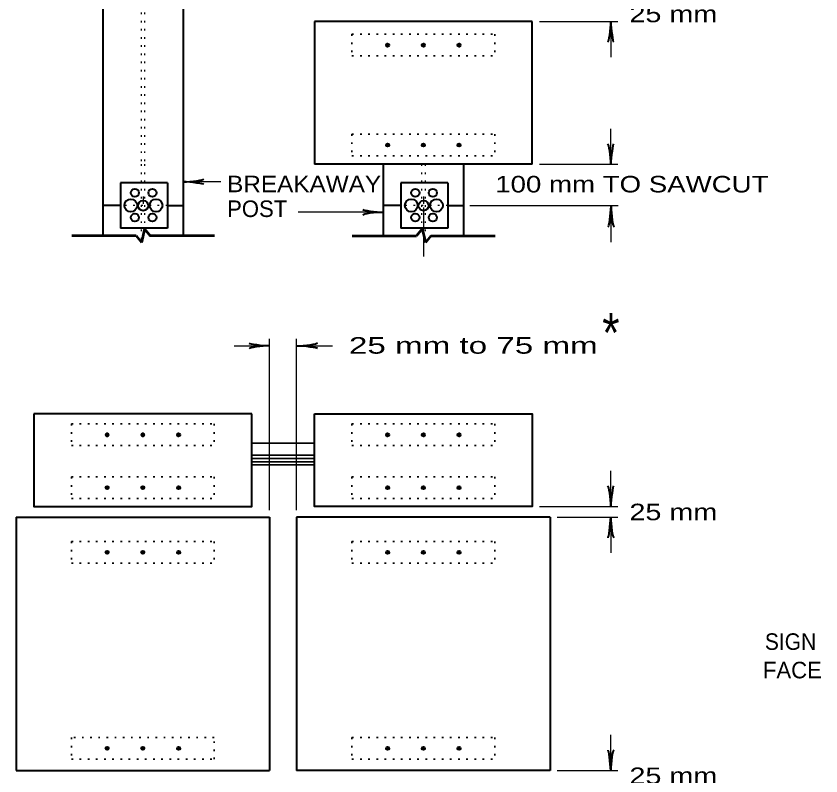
# Model space of a CAD drawing. Extents: x 851 to 1706, y -23 to 521.
# Drawn here: x 1210.4 to 1358.3, y 164.2 to 303.9 of the extents above; entities that cross this region are included whole.
import ezdxf
from ezdxf.enums import TextEntityAlignment as Align

# ---------------------------------------------------------------- set-up
doc = ezdxf.new("R2010")
doc.units = 0
doc.linetypes.add('DOTTED', pattern=[1.5, 0.3, -1.2])
doc.layers.add('1', color=7, linetype='Continuous', lineweight=35)

msp = doc.modelspace()

# ---------------------------------------------------------------- hatches: boundary and pattern name
at = {"layer": '1'}
for points in [[(1278.961, 298.572, 1), (1278.39, 298.572, 1)], [(1285.522, 298.572, 1), (1284.951, 298.572, 1)], [(1292.083, 298.572, 1), (1291.512, 298.572, 1)], [(1278.961, 280.202, 1), (1278.39, 280.202, 1)], [(1285.522, 280.202, 1), (1284.951, 280.202, 1)], [(1292.083, 280.202, 1), (1291.512, 280.202, 1)], [(1227.43, 226.939, 1), (1226.859, 226.939, 1)], [(1233.991, 226.939, 1), (1233.42, 226.939, 1)], [(1240.552, 226.939, 1), (1239.981, 226.939, 1)], [(1278.961, 226.939, 1), (1278.39, 226.939, 1)], [(1285.522, 226.939, 1), (1284.951, 226.939, 1)], [(1292.083, 226.939, 1), (1291.512, 226.939, 1)], [(1227.43, 217.207, 1), (1226.859, 217.207, 1)], [(1233.991, 217.207, 1), (1233.42, 217.207, 1)], [(1240.552, 217.207, 1), (1239.981, 217.207, 1)], [(1278.961, 217.207, 1), (1278.39, 217.207, 1)], [(1285.522, 217.207, 1), (1284.951, 217.207, 1)], [(1292.083, 217.207, 1), (1291.512, 217.207, 1)], [(1227.43, 205.315, 1), (1226.859, 205.315, 1)], [(1233.991, 205.315, 1), (1233.42, 205.315, 1)], [(1240.552, 205.315, 1), (1239.981, 205.315, 1)], [(1278.961, 205.315, 1), (1278.39, 205.315, 1)], [(1285.522, 205.315, 1), (1284.951, 205.315, 1)], [(1292.083, 205.315, 1), (1291.512, 205.315, 1)], [(1227.43, 169.284, 1), (1226.859, 169.284, 1)], [(1233.991, 169.284, 1), (1233.42, 169.284, 1)], [(1240.552, 169.284, 1), (1239.981, 169.284, 1)], [(1278.961, 169.284, 1), (1278.39, 169.284, 1)], [(1285.522, 169.284, 1), (1284.951, 169.284, 1)], [(1292.083, 169.284, 1), (1291.512, 169.284, 1)]]:
    msp.add_hatch(color=256, dxfattribs=at).paths.add_polyline_path(points)

# ---------------------------------------------------------------- linework, layer by layer
at = {"layer": '1', "lineweight": 40}
for p, q in [((1226.324, 378.043), (1226.324, 276.675)), ((1241.087, 378.043), (1241.087, 276.675)), ((1265.226, 302.919), (1265.226, 276.675)), ((1305.248, 302.919), (1265.226, 302.919)), ((1265.226, 302.919), (1265.226, 276.675)), ((1305.248, 276.675), (1305.248, 302.919)), ((1305.248, 276.675), (1305.248, 302.919)), ((1226.324, 276.675), (1226.324, 263.553)), ((1241.087, 276.675), (1241.087, 263.553)), ((1305.248, 276.675), (1265.226, 276.675)), ((1305.248, 276.675), (1265.226, 276.675)), ((1277.856, 276.675), (1277.856, 263.553)), ((1292.618, 276.675), (1292.618, 263.553)), ((1238.216, 273.285), (1229.577, 273.285)), ((1229.577, 273.285), (1229.577, 264.92)), ((1238.216, 273.285), (1238.216, 264.92)), ((1289.72, 273.285), (1281.081, 273.285)), ((1281.081, 273.285), (1281.081, 264.92)), ((1289.72, 273.285), (1289.72, 264.92)), ((1229.577, 269.075), (1226.379, 269.075)), ((1238.216, 269.075), (1241.141, 269.075)), ((1281.081, 269.075), (1277.91, 269.075)), ((1289.72, 269.075), (1292.672, 269.075)), ((1238.216, 264.92), (1229.577, 264.92)), ((1289.72, 264.92), (1281.081, 264.92)), ((1253.717, 230.821), (1213.695, 230.821)), ((1210.414, 211.794), (1256.997, 211.794)), ((1210.414, 211.794), (1210.414, 165.211)), ((1256.997, 211.794), (1256.997, 165.211)), ((1308.528, 211.794), (1261.945, 211.794)), ((1261.945, 211.794), (1261.945, 165.211)), ((1308.528, 211.794), (1308.528, 165.211)), ((1210.414, 165.211), (1256.997, 165.211)), ((1308.528, 165.211), (1261.945, 165.211))]:
    msp.add_line(p, q, dxfattribs=at)
at = {"layer": '1', "linetype": 'DOTTED', "lineweight": 25}
for p, q in [((1233.377, 378.043), (1233.377, 276.675)), ((1234.033, 378.043), (1234.033, 276.675)), ((1298.359, 300.568), (1298.359, 296.577)), ((1298.359, 282.197), (1298.359, 278.233)), ((1298.359, 282.197), (1298.359, 278.206)), ((1233.377, 276.675), (1233.377, 262.214)), ((1234.033, 276.675), (1234.033, 264.783)), ((1284.909, 276.675), (1284.909, 264.783)), ((1285.565, 276.675), (1285.565, 262.214)), ((1238.216, 269.075), (1229.577, 269.075)), ((1289.72, 269.075), (1281.081, 269.075)), ((1298.359, 228.934), (1298.359, 224.943)), ((1298.359, 171.28), (1298.359, 167.288))]:
    msp.add_line(p, q, dxfattribs=at)
at = {"layer": '1', "lineweight": 25}
for p, q in [((1306.56, 302.919), (1320.994, 302.919)), ((1319.682, 302.919), (1319.682, 296.358)), ((1319.682, 276.648), (1319.682, 283.209)), ((1306.56, 276.675), (1320.994, 276.675)), ((1248.003, 273.449), (1241.141, 273.449)), ((1233.76, 270.716), (1233.76, 269.403)), ((1285.291, 270.716), (1285.291, 269.403)), ((1277.91, 267.845), (1262.253, 267.845)), ((1285.291, 268.747), (1285.291, 259.726)), ((1293.766, 269.075), (1321.049, 269.075)), ((1319.736, 262.35), (1319.736, 268.911)), ((1256.997, 213.106), (1256.997, 244.599)), ((1261.945, 213.106), (1261.945, 244.599)), ((1250.462, 243.287), (1257.023, 243.287)), ((1261.999, 243.287), (1268.56, 243.287)), ((1319.682, 213.762), (1319.682, 220.323)), ((1306.56, 213.762), (1320.994, 213.762)), ((1309.84, 211.794), (1320.994, 211.794)), ((1319.682, 211.794), (1319.682, 205.233)), ((1319.682, 165.211), (1319.682, 171.772)), ((1309.84, 165.211), (1320.994, 165.211))]:
    msp.add_line(p, q, dxfattribs=at)
at = {"layer": '1', "linetype": 'DOTTED'}
for p, q in [((1272.115, 300.568), (1298.359, 300.568)), ((1272.115, 300.568), (1272.115, 296.577)), ((1298.359, 300.568), (1298.359, 296.577)), ((1272.115, 296.577), (1298.359, 296.577)), ((1272.115, 282.197), (1298.359, 282.197)), ((1272.115, 282.197), (1272.115, 278.206)), ((1298.359, 282.197), (1298.359, 278.206)), ((1272.115, 278.206), (1298.359, 278.206)), ((1220.583, 228.934), (1246.828, 228.934)), ((1220.583, 228.934), (1220.583, 224.943)), ((1246.828, 228.934), (1246.828, 224.943)), ((1272.115, 228.934), (1298.359, 228.934)), ((1272.115, 228.934), (1272.115, 224.943)), ((1298.359, 228.934), (1298.359, 224.943)), ((1220.583, 224.943), (1246.828, 224.943)), ((1272.115, 224.943), (1298.359, 224.943)), ((1220.583, 219.202), (1246.828, 219.202)), ((1220.583, 219.202), (1220.583, 215.211)), ((1246.828, 219.202), (1246.828, 215.211)), ((1272.115, 219.202), (1298.359, 219.202)), ((1272.115, 219.202), (1272.115, 215.211)), ((1298.359, 219.202), (1298.359, 215.211)), ((1220.583, 215.211), (1246.828, 215.211)), ((1272.115, 215.211), (1298.359, 215.211)), ((1220.583, 207.31), (1246.828, 207.31)), ((1220.583, 207.31), (1220.583, 203.319)), ((1246.828, 207.31), (1246.828, 203.319)), ((1272.115, 207.31), (1298.359, 207.31)), ((1272.115, 207.31), (1272.115, 203.319)), ((1298.359, 207.31), (1298.359, 203.319)), ((1220.583, 203.319), (1246.828, 203.319)), ((1272.115, 203.319), (1298.359, 203.319)), ((1272.115, 171.28), (1298.359, 171.28)), ((1272.115, 171.28), (1272.115, 167.288)), ((1298.359, 171.28), (1298.359, 167.288)), ((1272.115, 167.288), (1298.359, 167.288))]:
    msp.add_line(p, q, dxfattribs=at)
at = {"layer": '1', "lineweight": 53}
for p, q in [((1234.033, 264.783), (1233.432, 262.268)), ((1234.033, 264.783), (1235.072, 263.499)), ((1284.991, 264.783), (1283.979, 263.499)), ((1284.991, 264.783), (1285.619, 262.268)), ((1232.448, 263.499), (1220.638, 263.499)), ((1232.448, 263.499), (1233.432, 262.268)), ((1246.882, 263.499), (1235.072, 263.499)), ((1272.169, 263.499), (1283.979, 263.499)), ((1286.604, 263.499), (1285.619, 262.268)), ((1286.604, 263.499), (1298.413, 263.499))]:
    msp.add_line(p, q, dxfattribs=at)
at = {"layer": '1'}
for p, q in [((1253.717, 225.381), (1265.226, 225.381)), ((1253.717, 223.166), (1265.226, 223.166)), ((1265.226, 222.565), (1253.717, 222.565)), ((1265.226, 221.963), (1253.717, 221.963)), ((1253.717, 221.389), (1265.226, 221.389))]:
    msp.add_line(p, q, dxfattribs=at)
at = {"layer": '1', "lineweight": 40}
msp.add_lwpolyline([(1213.695, 230.821), (1213.695, 213.762), (1253.717, 213.762), (1253.717, 230.821)], dxfattribs=at)
msp.add_lwpolyline([(1265.226, 230.821), (1305.248, 230.821), (1305.248, 213.762), (1265.226, 213.762)], close=True, dxfattribs=at)
at = {"layer": '1', "linetype": 'DOTTED'}
msp.add_lwpolyline([(1246.828, 171.28), (1220.583, 171.28), (1220.583, 167.288), (1246.828, 167.288)], close=True, dxfattribs=at)
at = {"layer": '1', "lineweight": 40}
for centre, radius in [((1278.676, 298.572), 0.286), ((1285.237, 298.572), 0.286), ((1291.798, 298.572), 0.286), ((1278.676, 280.202), 0.286), ((1285.237, 280.202), 0.286), ((1291.798, 280.202), 0.286), ((1232.236, 271.415), 0.745), ((1235.459, 271.415), 0.745), ((1283.756, 271.415), 0.745), ((1286.979, 271.415), 0.745), ((1231.493, 269.093), 1.17), ((1233.765, 269.065), 0.927), ((1236.13, 269.093), 1.17), ((1283.013, 269.093), 1.17), ((1285.285, 269.065), 0.927), ((1287.65, 269.093), 1.17), ((1232.236, 266.878), 0.745), ((1235.459, 266.878), 0.745), ((1283.756, 266.878), 0.745), ((1286.979, 266.878), 0.745), ((1227.145, 226.939), 0.286), ((1233.706, 226.939), 0.286), ((1240.266, 226.939), 0.286), ((1278.676, 226.939), 0.286), ((1285.237, 226.939), 0.286), ((1291.798, 226.939), 0.286), ((1227.145, 217.207), 0.286), ((1233.706, 217.207), 0.286), ((1240.266, 217.207), 0.286), ((1278.676, 217.207), 0.286), ((1285.237, 217.207), 0.286), ((1291.798, 217.207), 0.286), ((1227.145, 205.315), 0.286), ((1233.706, 205.315), 0.286), ((1240.266, 205.315), 0.286), ((1278.676, 205.315), 0.286), ((1285.237, 205.315), 0.286), ((1291.798, 205.315), 0.286), ((1227.145, 169.284), 0.286), ((1233.706, 169.284), 0.286), ((1240.266, 169.284), 0.286), ((1278.676, 169.284), 0.286), ((1285.237, 169.284), 0.286), ((1291.798, 169.284), 0.286)]:
    msp.add_circle(centre, radius, dxfattribs=at)
for centre, major_axis, ratio, start_param, end_param in [((1319.307, 301.493), (0.205, 2.343), 0.122415, 3.1415927, 5.386832), ((1319.307, 301.493), (0.205, 2.343), 0.122415, 3.1415927, 5.386832), ((1319.947, 301.455), (-0.23, 2.305), 0.07063, 0.8650754, 3.1424706), ((1319.947, 301.455), (-0.23, 2.305), 0.07063, 0.8650754, 3.1424706), ((1319.307, 278.069), (0.205, -2.343), 0.122415, 0.8963533, 3.1415927), ((1319.947, 278.108), (-0.23, -2.305), 0.07063, 3.1407148, 5.41811), ((1242.569, 273.81), (-2.343, -0.205), 0.122415, 0.8963533, 3.1415927), ((1242.569, 273.81), (-2.343, -0.205), 0.122415, 0.8963533, 3.1415927), ((1242.608, 273.17), (-2.305, 0.23), 0.07063, 3.1407148, 5.41811), ((1242.608, 273.17), (-2.305, 0.23), 0.07063, 3.1407148, 5.41811), ((1276.466, 267.488), (2.343, 0.205), 0.122415, 0.8963533, 3.1415927), ((1276.427, 268.128), (2.305, -0.23), 0.07063, 3.1407148, 5.41811), ((1319.446, 267.451), (0.23, 2.305), 0.07063, 3.1407148, 5.41811), ((1320.087, 267.49), (-0.205, 2.343), 0.122415, 0.8963533, 3.1415927), ((1255.582, 242.93), (2.343, 0.205), 0.122415, 0.8963533, 3.1415927), ((1255.582, 242.93), (2.343, 0.205), 0.122415, 0.8963533, 3.1415927), ((1255.543, 243.57), (2.305, -0.23), 0.07063, 3.1407148, 5.41811), ((1255.543, 243.57), (2.305, -0.23), 0.07063, 3.1407148, 5.41811), ((1263.418, 243.655), (-2.343, -0.205), 0.122415, 0.8963533, 3.1415927), ((1263.456, 243.015), (-2.305, 0.23), 0.07063, 3.1407148, 5.41811), ((1319.307, 215.2), (0.205, -2.343), 0.122415, 0.8963533, 3.1415927), ((1319.307, 215.2), (0.205, -2.343), 0.122415, 0.8963533, 3.1415927), ((1319.947, 215.238), (-0.23, -2.305), 0.07063, 3.1407148, 5.41811), ((1319.947, 215.238), (-0.23, -2.305), 0.07063, 3.1407148, 5.41811), ((1319.392, 210.329), (0.23, 2.305), 0.07063, 3.1407148, 5.41811), ((1319.392, 210.329), (0.23, 2.305), 0.07063, 3.1407148, 5.41811), ((1320.032, 210.368), (-0.205, 2.343), 0.122415, 0.8963533, 3.1415927), ((1320.032, 210.368), (-0.205, 2.343), 0.122415, 0.8963533, 3.1415927), ((1319.392, 166.687), (0.23, -2.305), 0.07063, 0.8650754, 3.1424706), ((1319.392, 166.687), (0.23, -2.305), 0.07063, 0.8650754, 3.1424706), ((1320.032, 166.648), (-0.205, -2.343), 0.122415, 3.1415927, 5.386832), ((1320.032, 166.648), (-0.205, -2.343), 0.122415, 3.1415927, 5.386832)]:
    msp.add_ellipse(centre, major_axis=major_axis, ratio=ratio, start_param=start_param, end_param=end_param, dxfattribs=at)

# ---------------------------------------------------------------- texts
at = {"layer": '1'}
for s, height, width, p in [('25 mm', 3.037, 1.3, (1331.165, 302.778)), ('100 mm TO SAWCUT', 3.037, 1.25, (1323.543, 271.493)), ('*', 7.2, 0.85, (1319.696, 242.103)), ('25 mm to 75 mm', 3.037, 1.5, (1294.412, 241.85)), ('25 mm', 3.037, 1.3, (1331.165, 211.232)), ('SIGN', 3.037, 0.95, (1352.698, 187.405)), ('25 mm', 3.037, 1.3, (1331.165, 162.735))]:
    msp.add_text(s, height=height, dxfattribs=dict(at, width=width)).set_placement(p, align=Align.CENTER)
at = {"layer": '1', "width": 1.1}
msp.add_text('BREAKAWAY ', height=3.037, dxfattribs=at).set_placement((1249.178, 271.533))
at = {"layer": '1'}
msp.add_text('POST', height=3.037, dxfattribs=at).set_placement((1249.178, 266.976))
msp.add_text('FACE', height=3.037, dxfattribs=at).set_placement((1353.034, 182.172), align=Align.CENTER)

doc.saveas('drawing.dxf')
